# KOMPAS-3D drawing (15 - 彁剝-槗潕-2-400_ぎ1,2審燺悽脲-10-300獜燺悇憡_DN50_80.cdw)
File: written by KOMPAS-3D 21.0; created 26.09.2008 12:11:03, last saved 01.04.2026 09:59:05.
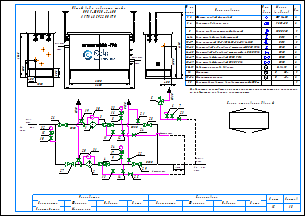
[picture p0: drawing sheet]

Sheets 1-2: A3, landscape

Document properties: Наименование: Макро:21; Автор: RaskoAdmin; Форматы листов документа: 2xA3; Полное имя файла: \\UR38nt01\Departments\КТО\КБ ПУРДГ\Заявки\Прайс-лист на типовые шкафы ГРПШ\ПРДГ_стандарт_20_03_2026\ПРДГ с РДСК\ПРДГ-ШУЭО-2-400_до1,2МПа_Рвых-10-300кПа_РДСК_DN50_80.cdw

Title block, sheet 1: Наименование: Пункт учета газа / ПУГ-Ш-400-Р / ЛГТИ.485922.001ТУ; designation: ЛГТИ.03.4411141; sheet number: 1; Количество листов документа: 2; organisation: ООО "ЭЛЬСТЕР Газэлектроника"; Форматы листов документа: A3; stored path: C:\Рабочие документы\Компас\ПУГ\Схема.cdw; Разработал: Устинов; Проверил: Кошкин; Утвердил: Кошкин
Title block, sheet 2: sheet number: 2; stored path: D:\Рабочие документы\Заявки\ПУРДГ\ПУРДГ-ШУЭО-2-100-Р 4411220.cdw; designation, second copy: ЛГТИ.03.4411141-

Views: Вид 1, Вид 2
Referenced files: wcvoit.frw
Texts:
  Normal
  Вход
  газа
  PDI
  Выход
  Р=     кПа
  DN80
  DN50
  DN20
  Импульс DN20
  ≥5DN
  HYSWLongFangSong
  № на
  схеме
  Усл.
  обозн.
  Марка
  (модель)
  Кол.
  Фильтр газовый фланцевый
  ФГ 16-50
  Регулятор давления газа
  РДCК-50
  Клапан предохранительный сбросной
  КПС DN20
  Кран шаровой газовый латунный
  DN15
  Кран кнопочный VE-РАСКО-НЗ-1,6-G1/2-М20
  Кран шаровой "под приварку" штуцерный DN20 PN16
  Кран шаровой "под приварку" штуцерный п/п DN20 PN16
  Кран шаровой фланцевый DN50 PN16
  Кран шаровой фланцевый DN80 PN16
  Индикатор перепада давления
  Delta 15
  Манометр
  Манометр-напоромер
  Электрообогреватель взрывозащищенный 400Вт
  0...     МПа
  0...     кПа
  Общий вид и габариты шкафа
  ПРДГ-ШУЭО-2-400
  Выход газа
  Вход газа
  Схема открывания дверей
  Р=        МПа
  logo-rasko-ge.png
  Предприятие изготовитель может заменять комплектующие на аналогичные,
  не ухудшающие заявленных характеристик.
  Должность
  Конструктор
  Фамилия
  Подпись
  Дата
  Согласовано
  Максимкин
  Лист
  Листов
  POLYLINE_STYLE_0.18_RGB_0_0_0
  POLYLINE_STYLE_0.50_RGB_0_0_0
  POLYLINE_STYLE_0.34_RGB_0_0_0
  PHANTOM_RGB_0_0_0_SC_1_THICK_0.18
  K5LT_THIN_RGB_0_0_0_THICK_0.18
  K5LT32769_RGB_0_0_0_THICK_0.18
  K5LT12_RGB_0_0_0_SC_1_THICK_0.18
  K5LT_DASHED_RGB_0_0_0_SC_1_THICK_0.18
  ACISOTGL_RGB_0_0_0_SC_0.8_THICK_0.25
  CONTINUOUS_RGB_0_127_31_THICK_0.3
  CONTINUOUS_RGB_0_0_255_THICK_0.35
  CONTINUOUS_RGB_255_0_0_THICK_0.35
  POLYLINE_STYLE_0.25_RGB_0_0_0
  CONTINUOUS_RGB_0_0_0_THICK_0.5
  POLYLINE_STYLE_0.35_RGB_0_0_255
  CONTINUOUS_RGB_0_0_0_THICK_0.4
  CONTINUOUS_RGB_0_0_0_THICK_0.35
  Без оформления
Dimensions and other numbers on the sheet: 1; 2; 3; 4; 5; 10; 27; 28; 29; 23; 8; 12; 19; 20; 21; 22; 25; 24; 30; 31; 15; 16; 26; 6; 7; 11; 14; 13; 33; 1, 2; 3, 4; 6-14; 9; 15-17; 18-23; 24-25; 26-27; 28-29; 30-31; 32; 33-34; 35; 400; 1050; 500; 305; 2300; 1565; 2600; 17; 34; 1000; 4130; 18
